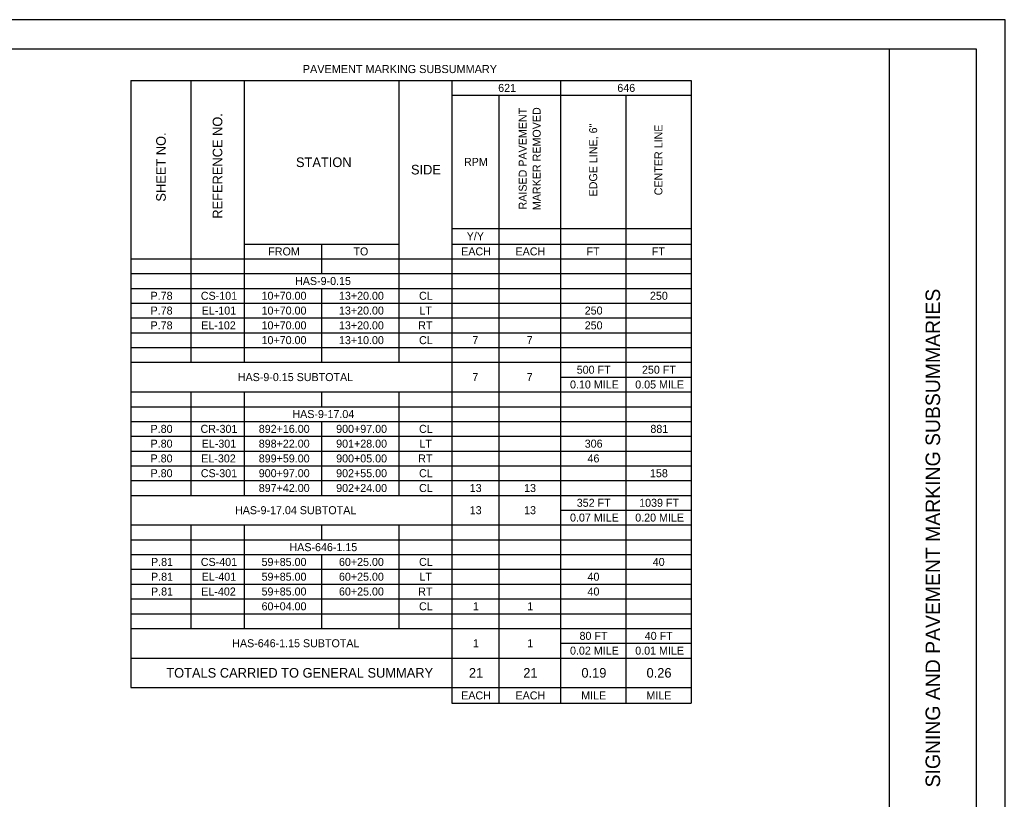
# Model space of a CAD drawing. Extents: x 0 to 1700, y 0 to 1100.
# Drawn here: x 850 to 1700, y 428 to 1100 of the extents above; entities that cross this region are included whole.
import ezdxf

# ---------------------------------------------------------------- set-up
doc = ezdxf.new("R2010")
doc.units = 0
for name, color, linetype in [('SH_Border', 7, 'Continuous'), ('SH_Cut_Line', 7, 'Continuous'), ('SH_Data', 7, 'Continuous'), ('SH_Text', 7, 'Continuous')]:
    doc.layers.add(name, color=color, linetype=linetype)

msp = doc.modelspace()

# ---------------------------------------------------------------- linework, layer by layer
at = {"layer": 'SH_Border'}
msp.add_line((1600, 25), (1600, 1075), dxfattribs=at)
msp.add_lwpolyline([(75, 1075), (1675, 1075), (1675, 25), (75, 25)], close=True, dxfattribs=at)
at = {"layer": 'SH_Cut_Line'}
msp.add_lwpolyline([(0, 0), (1700, 0), (1700, 1100), (0, 1100)], close=True, dxfattribs=at)
at = {"layer": 'SH_Text'}
for p, q in [((945.95, 1047.58), (1428.95, 1047.58)), ((945.95, 1047.58), (945.95, 524.08)), ((997.7, 1047.58), (997.7, 804.58)), ((1043.45, 1047.58), (1043.45, 804.58)), ((1176.95, 1047.58), (1176.95, 804.58)), ((1222.7, 1047.58), (1222.7, 510.58)), ((1316.45, 1047.58), (1316.45, 510.58)), ((1428.95, 1047.58), (1428.95, 510.58)), ((1222.7, 1034.83), (1428.95, 1034.83)), ((1263.2, 1034.83), (1263.2, 510.58)), ((1372.7, 1034.83), (1372.7, 510.58)), ((1222.7, 920.08), (1428.95, 920.08)), ((1043.45, 906.58), (1176.95, 906.58)), ((1110.2, 906.58), (1110.2, 881.08)), ((1222.7, 906.58), (1428.95, 906.58)), ((945.95, 893.83), (1428.95, 893.83)), ((945.95, 881.08), (1428.95, 881.08)), ((945.95, 868.33), (1428.95, 868.33)), ((1110.2, 868.33), (1110.2, 804.58)), ((945.95, 855.58), (1428.95, 855.58)), ((945.95, 842.83), (1428.95, 842.83)), ((945.95, 830.08), (1428.95, 830.08)), ((945.95, 817.33), (1428.95, 817.33)), ((945.95, 804.58), (1428.95, 804.58)), ((1316.45, 791.83), (1428.95, 791.83)), ((945.95, 779.08), (1428.95, 779.08)), ((997.7, 779.08), (997.7, 689.83)), ((1043.45, 779.08), (1043.45, 689.83)), ((1110.2, 779.08), (1110.2, 766.33)), ((1176.95, 779.08), (1176.95, 689.83)), ((945.95, 766.33), (1428.95, 766.33)), ((945.95, 753.58), (1428.95, 753.58)), ((1110.2, 753.58), (1110.2, 689.83)), ((945.95, 740.83), (1428.95, 740.83)), ((945.95, 728.08), (1428.95, 728.08)), ((945.95, 715.33), (1428.95, 715.33)), ((945.95, 702.58), (1428.95, 702.58)), ((945.95, 689.83), (1428.95, 689.83)), ((1316.45, 677.08), (1428.95, 677.08)), ((945.95, 664.33), (1428.95, 664.33)), ((997.7, 664.33), (997.7, 575.08)), ((1043.45, 664.33), (1043.45, 575.08)), ((1110.2, 664.33), (1110.2, 651.58)), ((1176.95, 664.33), (1176.95, 575.08)), ((945.95, 651.58), (1428.95, 651.58)), ((945.95, 638.83), (1428.95, 638.83)), ((1110.2, 638.83), (1110.2, 575.08)), ((945.95, 626.08), (1428.95, 626.08)), ((945.95, 613.33), (1428.95, 613.33)), ((945.95, 600.58), (1428.95, 600.58)), ((945.95, 587.83), (1428.95, 587.83)), ((945.95, 575.08), (1428.95, 575.08)), ((1316.45, 562.33), (1428.95, 562.33)), ((945.95, 549.58), (1428.95, 549.58)), ((945.95, 524.08), (1428.95, 524.08)), ((1222.7, 510.58), (1428.95, 510.58))]:
    msp.add_line(p, q, dxfattribs=at)

# ---------------------------------------------------------------- texts
at = {"layer": 'SH_Data'}
msp.add_text('SIGNING AND PAVEMENT MARKING SUBSUMMARIES', height=12.5, rotation=90, dxfattribs=at).set_placement((1643.75, 438.02))
at = {"layer": 'SH_Text'}
for s, height, p in [('PAVEMENT MARKING SUBSUMMARY', 7, (1094.14, 1053.98)), ('621', 6.9, (1262.67, 1037.75)), ('646', 6.9, (1365.42, 1037.75)), ('STATION', 8.28, (1088.25, 972.94)), ('RPM', 6.9, (1233.14, 974)), ('SIDE', 8.28, (1187.44, 966.56)), ('Y/Y', 6.9, (1235.5, 909.88)), ('FROM', 6.9, (1064.38, 896.75)), ('TO', 6.9, (1137.82, 896.75)), ('EACH', 6.9, (1230.75, 896.75)), ('EACH', 6.9, (1277.62, 896.75)), ('FT', 6.9, (1338.85, 896.75)), ('FT', 6.9, (1395.1, 896.75)), ('HAS-9-0.15', 6.9, (1087.47, 871.25)), ('P.78', 6.9, (962.87, 858.5)), ('CS-101', 6.9, (1006.2, 858.5)), ('10+70.00', 6.9, (1058.58, 858.5)), ('13+20.00', 6.9, (1125.33, 858.5)), ('CL', 6.9, (1194.42, 858.5)), ('250', 6.9, (1393.55, 858.5)), ('P.78', 6.9, (962.87, 845.75)), ('EL-101', 6.9, (1006.92, 845.75)), ('10+70.00', 6.9, (1058.58, 845.75)), ('13+20.00', 6.9, (1125.33, 845.75)), ('LT', 6.9, (1194.66, 845.75)), ('250', 6.9, (1337.3, 845.75)), ('P.78', 6.9, (962.87, 833)), ('EL-102', 6.9, (1006.57, 833)), ('10+70.00', 6.9, (1058.58, 833)), ('13+20.00', 6.9, (1125.33, 833)), ('RT', 6.9, (1193.69, 833)), ('250', 6.9, (1337.3, 833)), ('10+70.00', 6.9, (1058.58, 820.25)), ('13+10.00', 6.9, (1125.33, 820.25)), ('CL', 6.9, (1194.42, 820.25)), ('7', 6.9, (1240.37, 820.25)), ('7', 6.9, (1287.24, 820.25)), ('500 FT', 6.9, (1330.41, 794.75)), ('250 FT', 6.9, (1386.66, 794.75)), ('HAS-9-0.15 SUBTOTAL', 6.9, (1038.09, 788.38)), ('7', 6.9, (1240.37, 788.38)), ('7', 6.9, (1287.24, 788.38)), ('0.10 MILE', 6.9, (1324.61, 782)), ('0.05 MILE', 6.9, (1380.86, 782)), ('HAS-9-17.04', 6.9, (1085.18, 756.5)), ('P.80', 6.9, (962.86, 743.75)), ('CR-301', 6.9, (1005.96, 743.75)), ('892+16.00', 6.9, (1056.17, 743.75)), ('900+97.00', 6.9, (1122.92, 743.75)), ('CL', 6.9, (1194.42, 743.75)), ('881', 6.9, (1393.92, 743.75)), ('P.80', 6.9, (962.86, 731)), ('EL-301', 6.9, (1006.92, 731)), ('898+22.00', 6.9, (1056.17, 731)), ('901+28.00', 6.9, (1122.92, 731)), ('LT', 6.9, (1194.66, 731)), ('306', 6.9, (1337.29, 731)), ('P.80', 6.9, (962.86, 718.25)), ('EL-302', 6.9, (1006.57, 718.25)), ('899+59.00', 6.9, (1056.17, 718.25)), ('900+05.00', 6.9, (1122.92, 718.25)), ('RT', 6.9, (1193.69, 718.25)), ('46', 6.9, (1339.7, 718.25)), ('P.80', 6.9, (962.86, 705.5)), ('CS-301', 6.9, (1006.2, 705.5)), ('900+97.00', 6.9, (1056.17, 705.5)), ('902+55.00', 6.9, (1122.92, 705.5)), ('CL', 6.9, (1194.42, 705.5)), ('158', 6.9, (1393.56, 705.5)), ('897+42.00', 6.9, (1056.17, 692.75)), ('902+24.00', 6.9, (1122.92, 692.75)), ('CL', 6.9, (1194.42, 692.75)), ('13', 6.9, (1238.12, 692.75)), ('13', 6.9, (1285, 692.75)), ('HAS-9-17.04 SUBTOTAL', 6.9, (1035.68, 673.63)), ('13', 6.9, (1238.12, 673.63)), ('13', 6.9, (1285, 673.63)), ('352 FT', 6.9, (1330.41, 680)), ('1039 FT', 6.9, (1384.24, 680)), ('0.07 MILE', 6.9, (1324.61, 667.25)), ('0.20 MILE', 6.9, (1380.86, 667.25)), ('HAS-646-1.15', 6.9, (1082.65, 641.75)), ('P.81', 6.9, (963.24, 629)), ('CS-401', 6.9, (1006.2, 629)), ('59+85.00', 6.9, (1058.58, 629)), ('60+25.00', 6.9, (1125.33, 629)), ('CL', 6.9, (1194.42, 629)), ('40', 6.9, (1395.96, 629)), ('P.81', 6.9, (963.24, 616.25)), ('EL-401', 6.9, (1006.92, 616.25)), ('59+85.00', 6.9, (1058.58, 616.25)), ('60+25.00', 6.9, (1125.33, 616.25)), ('LT', 6.9, (1194.66, 616.25)), ('40', 6.9, (1339.71, 616.25)), ('P.81', 6.9, (963.24, 603.5)), ('EL-402', 6.9, (1006.57, 603.5)), ('59+85.00', 6.9, (1058.58, 603.5)), ('60+25.00', 6.9, (1125.33, 603.5)), ('RT', 6.9, (1193.69, 603.5)), ('40', 6.9, (1339.71, 603.5)), ('60+04.00', 6.9, (1058.58, 590.75)), ('CL', 6.9, (1194.42, 590.75)), ('1', 6.9, (1240.87, 590.75)), ('1', 6.9, (1287.75, 590.75)), ('80 FT', 6.9, (1332.82, 565.25)), ('40 FT', 6.9, (1389.07, 565.25)), ('HAS-646-1.15 SUBTOTAL', 6.9, (1033.27, 558.88)), ('1', 6.9, (1240.87, 558.88)), ('1', 6.9, (1287.75, 558.88)), ('0.02 MILE', 6.9, (1324.61, 552.5)), ('0.01 MILE', 6.9, (1380.86, 552.5)), ('TOTALS CARRIED TO GENERAL SUMMARY', 8.28, (976.44, 532.69)), ('21', 8.28, (1237.4, 532.69)), ('21', 8.28, (1284.28, 532.69)), ('0.19', 8.28, (1334.44, 532.69)), ('0.26', 8.28, (1390.6, 532.69)), ('EACH', 6.9, (1230.75, 513.88)), ('EACH', 6.9, (1277.62, 513.88)), ('MILE', 6.9, (1334.25, 513.88)), ('MILE', 6.9, (1390.5, 513.88))]:
    msp.add_text(s, height=height, dxfattribs=at).set_placement(p)
for s, height, p in [('RAISED PAVEMENT ', 6.9, (1287.24, 936.36)), ('MARKER REMOVED', 6.9, (1299.31, 935.79)), ('REFERENCE NO.', 8.28, (1024.72, 928.41)), ('EDGE LINE, 6"', 6.9, (1348.03, 947.63)), ('CENTER LINE', 6.9, (1404.28, 948.57)), ('SHEET NO.', 8.28, (975.97, 943.16))]:
    msp.add_text(s, height=height, rotation=90, dxfattribs=at).set_placement(p)

doc.saveas('drawing.dxf')
